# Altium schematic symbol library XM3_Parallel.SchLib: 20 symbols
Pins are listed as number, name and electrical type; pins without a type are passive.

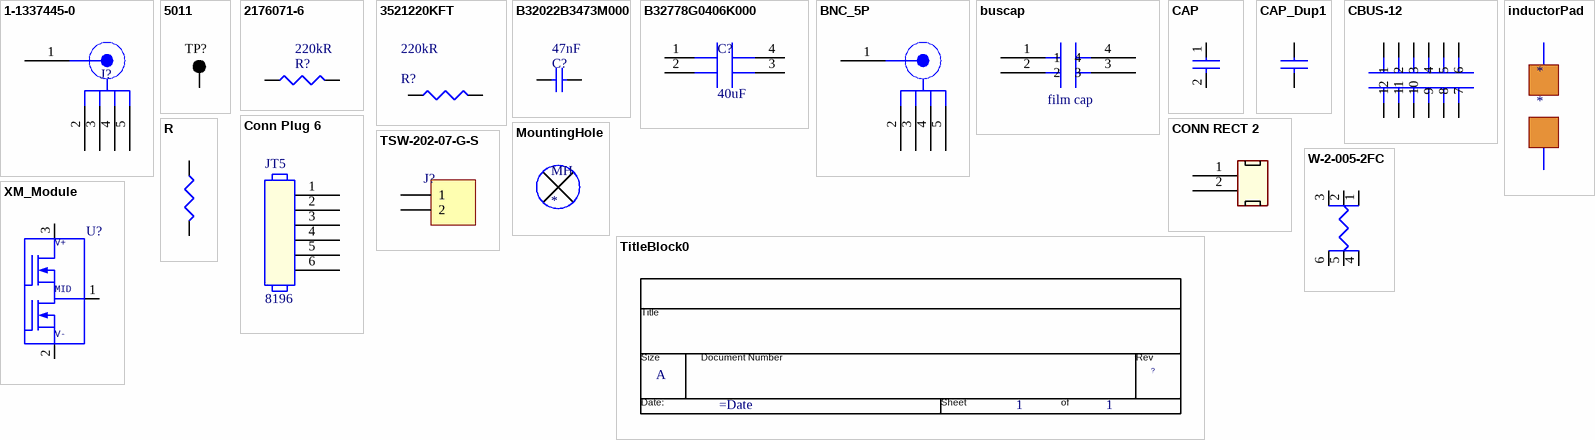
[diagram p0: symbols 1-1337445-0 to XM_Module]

## 1-1337445-0
designator J?  (value not drawn)
Conn BNC RCP 0Hz to 4GHz 50Ohm Solder ST Thru-Hole Silver Individual; Manufacturer: TE Connectivity; Manufacturer Part Number: 1-1337445-0; Body Material: Brass; Dielectric Material: PTFE; Impedance: 50R; Gender: Female; Connector Type: BNC,Jack; Insulation Resistance: 5GR; Number of Positions: 1; PCB Mount Retention: With; PCB Mounting Orientation: Vertical; Sealable: No (Without); Operating Frequency: 0 to 4Hz; PCB Thickness: 0.126inch
footprint FP-1-1337445-0-MFG
pins: 1 SIGNAL, 2 GND1, 3 GND2, 4 GND3, 5 GND4

## 5011
designator TP?  (value not drawn)
Test Point, Black, Through Hole, RoHS, Bulk; Manufacturer: Keystone
footprint KSTN-5011_V (Test Point, Dia 3.17mm)
pins: 1

## 2176071-6
designator R?  Resistance: 220kR  (hidden comment: *)
Res Thick Film 2512 220K Ohm 1% 2W ±100ppm/°C Molded SMD T/R; Manufacturer: TE Connectivity; Manufacturer Part Number: 2176071-6
footprint RESC6432X06N (Chip Resistor, 2-Leads, Body 6.35x3.20mm, IPC Medium Density)
pins: 1, 2

## 3521220KFT
designator R?  Resistance: 220kR  (hidden comment: *)
Res Thick Film 2512 220K Ohm 1% 2W ±100ppm/°C Molded SMD T/R; Manufacturer: TE Connectivity; Manufacturer Part Number: 3521220KFT; Voltage Rating: 250V; Number of Resistors: 1
footprint RESC6432X06N (Chip Resistor, 2-Leads, Body 6.35x3.20mm, IPC Medium Density)
pins: 1, 2

## B32022B3473M000
designator C?  Capacitance: 47nF  (hidden comment: *)
Cap Film 0.047uF 300VAC PP 20% 18 X 9 X 17.5mm RDL 15mm Bulk; Manufacturer: TDK EPCOS; Manufacturer Part Number: B32022B3473M000; Dielectric Material: Polypropylene; Voltage: 1.5kV; Insulation Resistance: 100R; Dissipation Factor: 1%; Lead Diameter: 0.8mm; Lead Length: 6mm
footprint B32022B3473M000
pins: 1, 2

## B32778G0406K000
designator C?  value 40uF  (hidden comment: *)
B32778G0406K000 Unchecked Film; Metallized Polypropylene; DC Link; C4AQ; Automotive Grade; 40 uF; 5%; 1; 50 Film Capacitors 8.13; Manufacturer: Kemet; Voltage Rating: 1500VDC; MFGR PN: C4AQSBW5220A3NJ
footprint C4AQSBW5220A3NJ (C4AQSBW5220A3NJ Unchecked Film; Metallized Polypropylene; DC Link; C4AQ; Automotive Grade; 22 uF; 5%; 1; 50 Film Capacitors 8.13)
pins: 1, 2, 3, 4

## BNC_5P
designator J?
footprint 40MLS
pins: 1 SIGNAL, 2 GND1, 3 GND2, 4 GND3, 5 GND4

## buscap
designator C?, comment film cap
footprint bus_cap
footprint C4AQSBW5220A3NJ (C4AQSBW5220A3NJ Unchecked Film; Metallized Polypropylene; DC Link; C4AQ; Automotive Grade; 22 uF; 5%; 1; 50 Film Capacitors 8.13)
pins: 1, 2, 3, 4

## CAP
designator C?
pins: 1, 2

## CAP_Dup1
designator C?
pins: 1, 2

## CBUS-12
designator C?
footprint CDIP-12
pins: 1, 2, 3, 4, 5, 6, 7, 8, 9, 10, 11, 12
1 alternate drawing of the same symbol

## Conn Plug 6
designator JT5, comment 8196
TERMINAL SCREW PC HEAVY DUTY; Manufacturer: Keystone Electronics; PART_NUMBER: TMP-963; CLASS: IO
footprint 8196
pins: 1, 2, 3, 4, 5, 6

## CONN RECT 2
designator J?
pins: 1, 2

## inductorPad
designator *

## MountingHole
designator MH
footprint MountingHole4mm5

## R
designator R?
pins: 1, 2

## TitleBlock0
designator *  Page Size: A  Page Number: 1  (hidden comment: *)  (graphical)

## TSW-202-07-G-S
designator J?  (value not drawn)
Headers & Wire Housings Classic PCB Header Strips, 0.100 pitch; Manufacturer: Samtec; Manufacturer Part Number: TSW-202-07-G-S; Number of Contacts: 2; Gender: Male; Max Current Rating: 7.6A; Max Voltage Rating (AC): 550V; Connector Type: Male Pin; Pitch: 5.08mm
footprint FP-TSW-202-07-G-S-MFG
pins: 1, 2

## W-2-005-2FC
designator R?
footprint W-2-005-2FC_3Hole
pins: 1, 2, 3, 4, 5, 6

## XM_Module
designator U?
footprint XM Module
pins: 1 V+, 2 V-, 3 MID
